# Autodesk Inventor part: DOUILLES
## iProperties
Created: 2004-11
Part Number: DOUILLES
Document SubType Name: Modeling
Designer: Bruno
Manufacturer: Standard
Standards Organization: Custom
Author: Bruno
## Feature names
1. Base1
2. Extrusion1
3. Extrusion2
4. Réseau circulaire1 [Circular Pattern]
